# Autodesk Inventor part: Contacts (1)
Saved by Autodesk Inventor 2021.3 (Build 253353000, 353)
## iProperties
Created: 2023-03
Part Number: Contacts (1)
Material: Generic
Document SubType Name: Modeling
Designer: AdminForWorker
Density: 1 g/cm^3
Appearance: Default
Title: Contacts (1)
Author: AdminForWorker
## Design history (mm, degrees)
feature "Body1"
body "Solid1"
